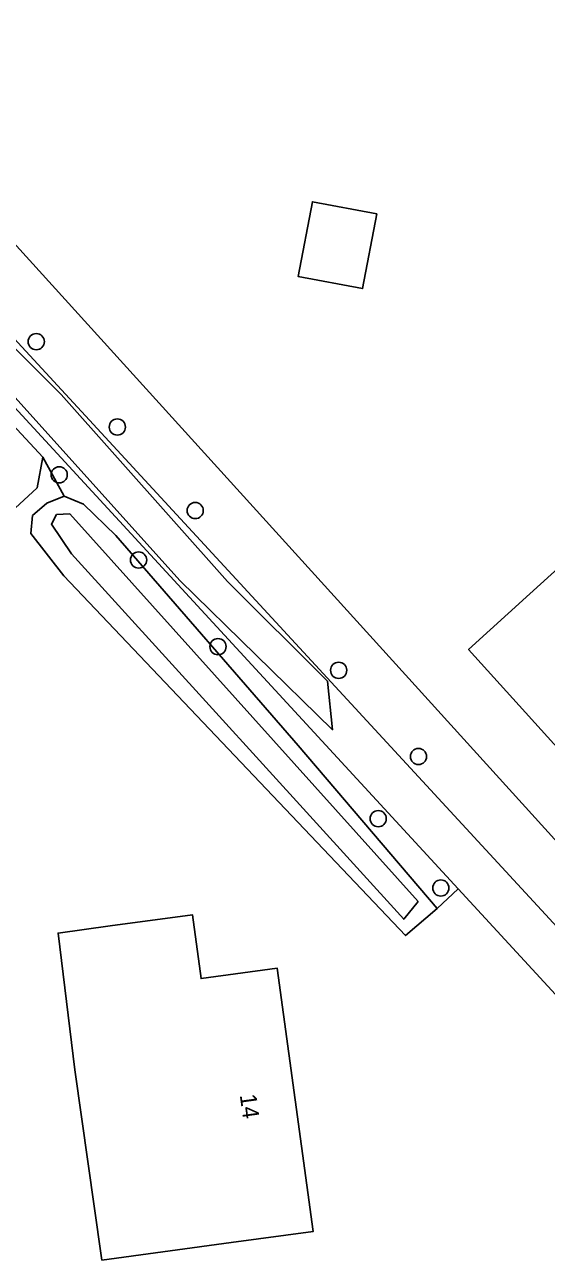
# Model space of a CAD drawing. Extents: x 157663 to 158496, y 379212 to 380934.
# Drawn here: x 158100.4 to 158131.9, y 380102.2 to 380176.7 of the extents above; entities that cross this region are included whole.
import ezdxf

# ---------------------------------------------------------------- set-up
doc = ezdxf.new("R2010")
doc.units = 0
for name, color, linetype in [('IMGEO_Boom', 7, 'Continuous'), ('IMGEO_Groenvoorziening', 7, 'Continuous'), ('IMGEO_Pand', 7, 'Continuous'), ('IMGEO_Pand_nummerreeks', 7, 'Continuous'), ('IMGEO_Voetpad_halfverhard', 7, 'Continuous'), ('IMGEO_Waterloop', 7, 'Continuous')]:
    doc.layers.add(name, color=color, linetype=linetype)

msp = doc.modelspace()

# ---------------------------------------------------------------- linework, layer by layer
at = {"layer": 'IMGEO_Boom'}
for centre in [(158101.122, 380157.571), (158106.012, 380152.421), (158102.508, 380149.54), (158110.712, 380147.385), (158107.296, 380144.403), (158112.085, 380139.177), (158119.366, 380137.75), (158124.18, 380132.549), (158121.751, 380128.801), (158125.528, 380124.62)]:
    msp.add_circle(centre, 0.489, dxfattribs=at)
at = {"layer": 'IMGEO_Groenvoorziening'}
for points in [[(158097.032, 380166.515), (158097.186, 380166.366), (158137.479, 380121.959)], [(158135.424, 380119.135), (158094.262, 380163.728), (158095.31, 380164.744)], [(158095.483, 380156.24), (158096.492, 380157.206), (158126.567, 380124.573)], [(158101.529, 380150.614), (158099.705, 380152.56), (158096.327, 380154.535)], [(158101.529, 380150.614), (158101.184, 380148.764), (158099.057, 380146.799), (158077.509, 380124.519)], [(158102.815, 380148.245), (158101.529, 380150.614)], [(158125.308, 380123.38), (158123.402, 380121.754), (158102.784, 380143.444), (158100.793, 380145.995), (158100.888, 380147.081), (158101.751, 380147.824), (158102.815, 380148.245)], [(158102.815, 380148.245), (158103.965, 380147.777), (158105.928, 380145.883), (158116.913, 380133.221), (158125.308, 380123.38)], [(158126.567, 380124.573), (158125.308, 380123.38)], [(158126.567, 380124.573), (158134.097, 380116.401)]]:
    msp.add_lwpolyline(points, dxfattribs=at)
at = {"layer": 'IMGEO_Pand'}
for points in [[(158121.665, 380165.271), (158120.805, 380160.768), (158116.921, 380161.51), (158117.781, 380166.013), (158121.665, 380165.271)], [(158142.773, 380148.217), (158146.129, 380144.511), (158139.393, 380138.41), (158141.044, 380136.587), (158134.641, 380130.789), (158127.199, 380139.006), (158130.905, 380142.363), (158140.337, 380150.906), (158142.773, 380148.217)], [(158105.072, 380102.165), (158105.034, 380102.45), (158103.452, 380113.66), (158102.439, 380121.903), (158105.59, 380122.333), (158110.544, 380123.008), (158111.069, 380119.154), (158115.664, 380119.781), (158117.828, 380103.903), (158112.874, 380103.228), (158105.072, 380102.165)]]:
    msp.add_lwpolyline(points, dxfattribs=at)
at = {"layer": 'IMGEO_Voetpad_halfverhard'}
msp.add_lwpolyline([(158062.721, 380196.88), (158064.874, 380195.438), (158066.25, 380194.061), (158068.729, 380191.108), (158084.514, 380173.448), (158095.781, 380161.339), (158098.736, 380158.241), (158102.622, 380154.388), (158112.654, 380143.096), (158118.682, 380137.087), (158119.003, 380134.166), (158109.781, 380143.162), (158098.916, 380155.218), (158092.416, 380162.001), (158083.144, 380172.008), (158072.622, 380183.749), (158066.754, 380190.041), (158064.49, 380191.827), (158064.058, 380192.021), (158063.398, 380192.063), (158062.889, 380191.853), (158062.485, 380191.389), (158061.718, 380190.062)], dxfattribs=at)
at = {"layer": 'IMGEO_Waterloop'}
msp.add_lwpolyline([(158124.158, 380123.798), (158103.143, 380147.177), (158102.345, 380147.143), (158102.04, 380146.565), (158103.245, 380144.781), (158123.291, 380122.737), (158124.158, 380123.798)], dxfattribs=at)

# ---------------------------------------------------------------- texts
at = {"layer": 'IMGEO_Pand_nummerreeks'}
msp.add_text('14', height=1, rotation=277.76098, dxfattribs=at).set_placement((158113.398, 380112.127))

doc.saveas('drawing.dxf')
